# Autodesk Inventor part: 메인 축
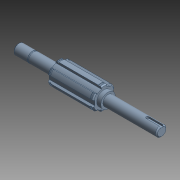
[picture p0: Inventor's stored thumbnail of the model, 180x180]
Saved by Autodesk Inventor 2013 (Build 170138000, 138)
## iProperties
Created: 2021-07
Part Number: 메인 축
Document SubType Name: 모델링
Designer: mdu
Mass: 168.566 g
Surface Area: 72.5104 cm^2
Volume: 21.4461 cm^3
Density: 7.86 g/cm^3
Material: 강철, 연강
변환 표준: STEP AP214IS
파일 이름: C:\Users\SeoGD\Desktop\?쒗뿕\硫붿씤 異?.stp
전처리기: Build: 253, Release: 2010 SP1 - Date: Wed 07/29/2009
전송 단위: 밀리미터
불확실성: 0.01
Author: mdu
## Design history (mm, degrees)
sketch "스케치1"
  geometry: L1 (-69.5, 0)-(69.5, 0); L2 (69.5, 0)-(69.5, 5); L3 (69.5, 5)-(55.5, 5); L4 (55.5, 5)-(55.5, 4.8); L5 (55.5, 4.8)-(54.35, 4.8); L6 (54.35, 4.8)-(54.35, 5); L7 (54.35, 5)-(30.5, 5); L8 (30.5, 5)-(30.5, 9); L9 (30.5, 9)-(-13.5, 9); L10 (-13.5, 9)-(-13.5, 7); L11 (-13.5, 7)-(-17.5, 7); L12 (-17.5, 7)-(-17.5, 5); L13 (-17.5, 5)-(-69.5, 5); L14 (-69.5, 5)-(-69.5, 0); 2 further points
  constraints: 28 end point, 9 parallel, 4 collinear, 2 perpendicular, 1 coincident, 1 horizontal, 1 midpoint
  dimensions: "d2" = 1.15 distance between parallel lines of L6 L4; "d3" = 10 diameter of L3 L1; "d4" = 9.6 diameter of L5 L1; "d6" = 44 distance between parallel lines of L10 L8; "d7" = 4 distance between parallel lines of L12 L10; "d8" = 14 diameter of L11 L1; "d9" = 18 diameter of L9 L1; "d33" = 52 distance from line of L12.end L14; "d37" = 39 distance between parallel lines of L8 L2; "d38" = 14 distance between parallel lines of L2 L4
revolve "회전1" sketch "스케치1" stored, may be unused: angle "d10" = 90 deg
sketch "스케치2"
  geometry: L1 (2.5, 10.712)-(2.5, 8.646); L2 (-2.5, 10.712)-(-2.5, 8.646); A1 r 9 centre (0, 0) between (2.5, 8.646) and (-2.5, 8.646) reference; A2 r 11 centre (0, 0) between (2.5, 10.712) and (-2.5, 10.712); 1 further point
  constraints: 4 end point, 4 point on circle, 2 parallel, 1 centre point, 1 coincident, 1 vertical
  dimensions: "d11" = 22 diameter of A2; "d12" = 5 distance between parallel lines of L1 L2
extrude "돌출1" join sketch "스케치2" stored distance "d13" = 10; taper "d14" = 0 deg
chamfer "모따기1" distance "d15" = 1; stored, may be unused: second distance "d16" = 2, angle "d17" = 45 deg
node "작업 평면1"
node "작업 평면2"
sketch "스케치3"
  geometry: L1 (2.5, 10.712)-(2.5, 10.198); L2 (-2.5, 10.712)-(-2.5, 10.198); A1 r 11 centre (0, 0) between (2.5, 10.712) and (-2.5, 10.712) reference; A2 r 10.5 centre (0, 0) between (2.5, 10.198) and (-2.5, 10.198); 1 further point
  constraints: 4 end point, 2 point on circle, 1 centre point, 1 coincident, 1 parallel, 1 vertical
  dimensions: "d19" = 21 diameter of A2
extrude "돌출2" cut sketch "스케치3" distance "d20" = 1.35; taper "d21" = 0 deg
node "작업 평면3"
sketch "스케치4"
  geometry: L1 (-26, -5)-(-26, 5) reference; L2 (-26, 1.5)-(-12.5, 1.5); L3 (-12.5, -1.5)-(-26, -1.5); A1 r 1.5 centre (-12.5, 0) between (-12.5, -1.5) and (-12.5, 1.5); 2 further points
  constraints: 4 end point, 2 perpendicular, 2 point on circle, 2 point on line, 2 tangent, 1 centre point, 1 horizontal alignment, 1 midpoint
  dimensions: "d25" = 3 distance between parallel lines of L3 L2; "d26" = 15 dimension on A1 L1
extrude "돌출3" cut sketch "스케치4" distance "d27" = 1.8; taper "d28" = 0 deg
chamfer "모따기2" distance "d29" = 1; stored, may be unused: second distance "d30" = 2, angle "d31" = 45 deg
node "솔리드1"
node "솔리드 본체"
node "곡면 본체"
mirror "대칭1"
pattern_circular "원형 패턴1" dims "d23" = 360 deg
node "솔리드2"
other parameters: "d18" = -1.65
